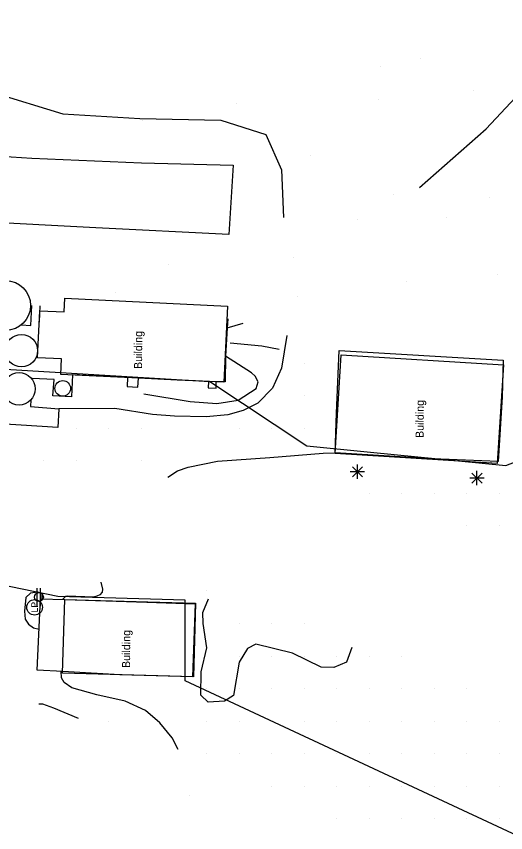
# Model space of a CAD drawing. Extents: x 19528164 to 19545171, y 7585743 to 7602745.
# Drawn here: x 19541683 to 19541984, y 7598916 to 7599418 of the extents above; entities that cross this region are included whole.
import ezdxf

# ---------------------------------------------------------------- set-up
doc = ezdxf.new("R2010")
doc.units = 0
for name, color, linetype in [('PhoAgStruc', 7, 'Continuous'), ('PhoBreakLine', 7, 'Continuous'), ('PhoBuilding', 7, 'Continuous'), ('PhoConcreteSlab', 7, 'Continuous'), ('PhoEdgeEntrancePaved', 7, 'Continuous'), ('PhoISAEPoints', 7, 'Continuous'), ('PhoNotesDesign', 7, 'Continuous'), ('PhoSurveyLimits', 7, 'Continuous'), ('PhoVegetation', 7, 'Continuous'), ('SurBreakLine', 7, 'Continuous'), ('SurEdgeEntranceUnpaved', 7, 'Continuous'), ('SurNaturalCells', 7, 'Continuous'), ('SurROWRail', 7, 'Continuous')]:
    doc.layers.add(name, color=color, linetype=linetype)

msp = doc.modelspace()

# ---------------------------------------------------------------- linework, layer by layer
at = {"layer": 'PhoAgStruc'}
for centre, radius in [((19541676.63, 7599240.45), 15.31), ((19541686.32, 7599212.7), 9.96), ((19541684.85, 7599189.24), 9.96), ((19541711.74, 7599189.49), 4.8)]:
    msp.add_circle(centre, radius, dxfattribs=at)
at = {"layer": 'PhoBreakLine'}
msp.add_line((19541751.4, 7599196.12), (19541717.68, 7599197.78), dxfattribs=at)
for points in [[(19541813.01, 7599232.3), (19541812.76, 7599226.71), (19541811.77, 7599209.21), (19541811.48, 7599193.45), (19541806.02, 7599193.45)], [(19541812.76, 7599226.71), (19541822.44, 7599229.62)], [(19541814.45, 7599217.59), (19541833.98, 7599215.72), (19541844.61, 7599213.59)], [(19541761.59, 7599186.11), (19541789.95, 7599181.37), (19541806.28, 7599180.25), (19541819.36, 7599182.32), (19541830.47, 7599189.5), (19541831.83, 7599193.45), (19541829.85, 7599197.03), (19541827.58, 7599199), (19541811.77, 7599209.21)], [(19541879.01, 7599149.94), (19541879.95, 7599174.32), (19541881.48, 7599212.82)], [(19541801.2, 7599193.69), (19541782.03, 7599194.5), (19541758.15, 7599195.79)], [(19541981.56, 7599184.36), (19541979.07, 7599144.6), (19541938.98, 7599146.13), (19541879.01, 7599149.94)], [(19541712.92, 7599059.72), (19541763.39, 7599058.11), (19541793.06, 7599057.05), (19541791.4, 7599012.18), (19541746.8, 7599013.45), (19541711.67, 7599015.6)]]:
    msp.add_lwpolyline(points, dxfattribs=at)
at = {"layer": 'PhoBuilding'}
for points in [[(19541713.02, 7599245.01), (19541812.85, 7599240.12), (19541810.56, 7599193.23), (19541710.54, 7599198.12), (19541711, 7599207.57), (19541696.21, 7599208.29), (19541697.63, 7599237.26), (19541712.61, 7599236.52)], [(19541978.6, 7599143.4), (19541878.98, 7599149.56), (19541882.73, 7599210.2), (19541982.35, 7599204.04)], [(19541712.92, 7599059.81), (19541793.27, 7599057.52), (19541791.99, 7599012.3), (19541711.64, 7599014.58)]]:
    msp.add_lwpolyline(points, close=True, dxfattribs=at)
at = {"layer": 'PhoConcreteSlab'}
for points in [[(19541751.4, 7599196.12), (19541751.22, 7599190.57), (19541757.91, 7599190.18), (19541758.15, 7599195.79)], [(19541801.2, 7599193.69), (19541800.97, 7599189.87), (19541805.92, 7599189.66), (19541806.02, 7599193.45)]]:
    msp.add_lwpolyline(points, dxfattribs=at)
at = {"layer": 'PhoEdgeEntrancePaved'}
for points in [[(19541686.25, 7599228.54), (19541692.18, 7599228.23), (19541692.82, 7599240.47)], [(19541697.61, 7599240.18), (19541697.16, 7599230.34), (19541697.29, 7599230.24)], [(19541708.71, 7599165.53), (19541673.35, 7599167.82), (19541673.13, 7599166.42), (19541666.04, 7599166.89), (19541666.9, 7599179.06), (19541672.59, 7599178.67), (19541674.19, 7599204.32), (19541652.81, 7599205.58)], [(19541717.68, 7599197.78), (19541717.16, 7599184.32), (19541705.7, 7599184.92), (19541706.39, 7599195.03), (19541692.86, 7599195.5), (19541692.85, 7599195.18)], [(19541692.18, 7599182.5), (19541691.96, 7599178.34), (19541709.25, 7599177), (19541708.71, 7599165.53)], [(19541711.67, 7599015.6), (19541695.9, 7599016.24), (19541698.04, 7599060.27), (19541712.92, 7599059.72)]]:
    msp.add_lwpolyline(points, dxfattribs=at)
at = {"layer": 'PhoISAEPoints'}
for p, q in [((19541860, 7599205), (19541860, 7599205)), ((19541860, 7599185), (19541860, 7599185)), ((19541720, 7599165), (19541720, 7599165)), ((19541740, 7599165), (19541740, 7599165)), ((19541760, 7599165), (19541760, 7599165)), ((19541820, 7599165), (19541820, 7599165)), ((19541840, 7599165), (19541840, 7599165)), ((19541860, 7599165), (19541860, 7599165)), ((19541700, 7599145), (19541700, 7599145)), ((19541720, 7599145), (19541720, 7599145)), ((19541760, 7599145), (19541760, 7599145)), ((19541900, 7599125), (19541900, 7599125)), ((19541920, 7599125), (19541920, 7599125)), ((19541940, 7599125), (19541940, 7599125)), ((19541960, 7599125), (19541960, 7599125)), ((19541980, 7599125), (19541980, 7599125)), ((19541960, 7599105), (19541960, 7599105)), ((19541980, 7599105), (19541980, 7599105)), ((19541800, 7599065), (19541800, 7599065)), ((19541820, 7599045), (19541820, 7599045)), ((19541840, 7599045), (19541840, 7599045)), ((19541860, 7599045), (19541860, 7599045)), ((19541820, 7599024.87), (19541820, 7599024.87)), ((19541840, 7599025), (19541840, 7599025)), ((19541860, 7599025), (19541860, 7599025)), ((19541880, 7599025), (19541880, 7599025)), ((19541900, 7599025), (19541900, 7599025)), ((19541920, 7599025), (19541920, 7599025)), ((19541800, 7599005), (19541800, 7599005)), ((19541820, 7599005), (19541820, 7599005)), ((19541840, 7599005), (19541840, 7599005)), ((19541860, 7599005), (19541860, 7599005)), ((19541880, 7599005), (19541880, 7599005)), ((19541900, 7599005), (19541900, 7599005)), ((19541920, 7599005), (19541920, 7599005)), ((19541940, 7599005), (19541940, 7599005)), ((19541960, 7599005), (19541960, 7599005)), ((19541740, 7598985), (19541740, 7598985)), ((19541800, 7598985), (19541800, 7598985)), ((19541820, 7598985), (19541820, 7598985)), ((19541840, 7598985), (19541840, 7598985)), ((19541860, 7598985), (19541860, 7598985)), ((19541880, 7598985), (19541880, 7598985)), ((19541900, 7598985), (19541900, 7598985)), ((19541920, 7598985), (19541920, 7598985)), ((19541940, 7598985), (19541940, 7598985)), ((19541960, 7598985), (19541960, 7598985)), ((19541980, 7598985), (19541980, 7598985)), ((19541800, 7598965), (19541800, 7598965)), ((19541820, 7598965), (19541820, 7598965)), ((19541840, 7598965), (19541840, 7598965)), ((19541860, 7598965), (19541860, 7598965)), ((19541880, 7598965), (19541880, 7598965)), ((19541900, 7598965), (19541900, 7598965)), ((19541920, 7598965), (19541920, 7598965)), ((19541940, 7598965), (19541940, 7598965)), ((19541960, 7598965), (19541960, 7598965)), ((19541980, 7598965), (19541980, 7598965)), ((19541840, 7598945), (19541840, 7598945)), ((19541860, 7598945), (19541860, 7598945)), ((19541880, 7598945), (19541880, 7598945)), ((19541900, 7598945), (19541900, 7598945)), ((19541920, 7598945), (19541920, 7598945)), ((19541940, 7598945), (19541940, 7598945)), ((19541960, 7598945), (19541960, 7598945)), ((19541980, 7598945), (19541980, 7598945)), ((19541880, 7598925), (19541880, 7598925)), ((19541900, 7598925), (19541900, 7598925)), ((19541920, 7598925), (19541920, 7598925)), ((19541940, 7598925), (19541940, 7598925)), ((19541960, 7598925), (19541960, 7598925)), ((19541980, 7598925), (19541980, 7598925))]:
    msp.add_line(p, q, dxfattribs=at)
at = {"layer": 'PhoSurveyLimits'}
msp.add_lwpolyline([(19541832.46, 7597845.39), (19542376.97, 7598092.17), (19542113.78, 7598846.31), (19542039.74, 7598891.68), (19541786.93, 7599009.68), (19541786.81, 7599059.41), (19541708.63, 7599061.66), (19541440.61, 7599116.66), (19541458.99, 7599214.49), (19541802.13, 7599193.81), (19541861.6, 7599154.2), (19541900.69, 7599150.34), (19541983.87, 7599142.12), (19543859.55, 7599862.07), (19543863.55, 7599896.16), (19543904.76, 7600247.38), (19543914.92, 7600450.3), (19543927.42, 7600632.62), (19543934.84, 7600743.15), (19543933.97, 7600882.93)], dxfattribs=at)
at = {"layer": 'PhoVegetation'}
for p, q in [((19541895.81, 7599141.37), (19541889.63, 7599135.18)), ((19541895.82, 7599135.18), (19541889.63, 7599141.36)), ((19541892.73, 7599133.9), (19541892.72, 7599142.65)), ((19541966.15, 7599130.03), (19541966.14, 7599138.78)), ((19541897.09, 7599138.28), (19541888.35, 7599138.27)), ((19541892.72, 7599138.27), (19541892.72, 7599138.27)), ((19541970.52, 7599134.41), (19541961.77, 7599134.4)), ((19541969.24, 7599131.32), (19541963.05, 7599137.49)), ((19541969.24, 7599137.5), (19541963.06, 7599131.31)), ((19541966.15, 7599134.4), (19541966.15, 7599134.4))]:
    msp.add_line(p, q, dxfattribs=at)
msp.add_lwpolyline([(19541889.31, 7599030.27), (19541885.91, 7599021.25), (19541878.21, 7599017.87), (19541870.42, 7599018.17), (19541852.86, 7599026.69), (19541830.36, 7599032.31), (19541825.2, 7599029.59), (19541820.04, 7599021.27), (19541816.52, 7599000.74), (19541811.05, 7598997.32), (19541800.94, 7598996.66), (19541796.47, 7599000.9), (19541796.77, 7599015.38), (19541800.25, 7599030.13), (19541797.96, 7599045.01), (19541797.74, 7599051.79), (19541801.27, 7599060.2)], dxfattribs=at)
at = {"layer": 'SurBreakLine'}
for points in [[(19541930.92, 7599313), (19541971.71, 7599349.07), (19541998.89, 7599377.98), (19542028.48, 7599429.47), (19542062.91, 7599497.51), (19542089.1, 7599544.66), (19542111.82, 7599579.57), (19542142.41, 7599612.54), (19542186.19, 7599651.15), (19542255.66, 7599698.78), (19542309.99, 7599746.63), (19542352.66, 7599799.39), (19542383.01, 7599842.6)], [(19541552.89, 7599257.18), (19541568.99, 7599308.86), (19541582.33, 7599341.92), (19541597.99, 7599363.5), (19541618.34, 7599376.13), (19541638.2, 7599379.64), (19541668.68, 7599371.35), (19541711.66, 7599358.25), (19541759.12, 7599355.39), (19541808.87, 7599354.27), (19541836.42, 7599345.57), (19541846.12, 7599323.84), (19541847.37, 7599294.48)], [(19541686.25, 7599228.54), (19541692.18, 7599228.23), (19541692.82, 7599240.47)], [(19541697.61, 7599240.18), (19541697.16, 7599230.34), (19541697.29, 7599230.24)], [(19541813.01, 7599232.3), (19541812.76, 7599226.71), (19541811.77, 7599209.21), (19541811.48, 7599193.45), (19541806.02, 7599193.45)], [(19541812.76, 7599226.71), (19541822.44, 7599229.62)], [(19541849.42, 7599221.94), (19541846.14, 7599201.99), (19541840.51, 7599189.56), (19541831.5, 7599180.49), (19541822.45, 7599175.97), (19541813.13, 7599173.29), (19541799.78, 7599172.1), (19541780.4, 7599172.52), (19541766.74, 7599173.42), (19541743.67, 7599177.07), (19541709.25, 7599177)], [(19541814.45, 7599217.59), (19541833.98, 7599215.72), (19541844.61, 7599213.59)], [(19541761.59, 7599186.11), (19541789.95, 7599181.37), (19541806.28, 7599180.25), (19541819.36, 7599182.32), (19541830.47, 7599189.5), (19541831.83, 7599193.45), (19541829.85, 7599197.03), (19541827.58, 7599199), (19541811.77, 7599209.21)], [(19541879.01, 7599149.94), (19541879.95, 7599174.32), (19541881.48, 7599212.82)], [(19541881.48, 7599212.82), (19541982.21, 7599206.84), (19541981.56, 7599184.36)], [(19541801.2, 7599193.69), (19541782.03, 7599194.5), (19541758.15, 7599195.79)], [(19541801.2, 7599193.69), (19541800.97, 7599189.87), (19541805.92, 7599189.66), (19541806.02, 7599193.45)], [(19541981.56, 7599184.36), (19541979.07, 7599144.6), (19541938.98, 7599146.13), (19541879.01, 7599149.94)], [(19541782.53, 7598967.59), (19541779.01, 7598974.79), (19541771.34, 7598984.02), (19541762.58, 7598991.54), (19541750.1, 7598997.3), (19541732.59, 7599001.27), (19541717.31, 7599005.54), (19541712.67, 7599008.73), (19541711.01, 7599011.66), (19541710.79, 7599015.63)]]:
    msp.add_lwpolyline(points, dxfattribs=at)
msp.add_lwpolyline([(19541813.63, 7599284.15), (19541732.13, 7599288.19), (19541658.22, 7599292.08), (19541613.98, 7599294.09), (19541616.39, 7599336.01), (19541692.81, 7599331), (19541760.01, 7599328.17), (19541816.47, 7599326.7)], close=True, dxfattribs=at)
at = {"layer": 'SurEdgeEntranceUnpaved'}
for p, q in [((19541931.17, 7599392.41), (19541931.17, 7599392.41)), ((19541906.61, 7599387.28), (19541906.61, 7599387.28)), ((19541964.22, 7599372.42), (19541964.22, 7599372.42)), ((19541818.73, 7599364.65), (19541818.73, 7599364.65)), ((19541905.35, 7599367.03), (19541905.35, 7599367.03)), ((19541760.55, 7599354.11), (19541760.55, 7599354.11)), ((19541864.06, 7599332.88), (19541864.06, 7599332.88)), ((19541914.72, 7599308.52), (19541914.72, 7599308.52)), ((19541974.09, 7599306.89), (19541974.09, 7599306.89)), ((19541947.61, 7599294.8), (19541947.61, 7599294.8)), ((19541892.56, 7599293.01), (19541892.56, 7599293.01)), ((19541853.39, 7599269.92), (19541853.39, 7599269.92)), ((19541776.71, 7599265.49), (19541776.71, 7599265.49)), ((19541978.45, 7599259.48), (19541978.45, 7599259.48)), ((19541922.85, 7599255.02), (19541922.85, 7599255.02)), ((19541744.01, 7599248.69), (19541744.01, 7599248.69)), ((19541855.93, 7599246.25), (19541855.93, 7599246.25)), ((19541860, 7599205), (19541860, 7599205)), ((19541860, 7599185), (19541860, 7599185)), ((19541860, 7599165), (19541860, 7599165)), ((19541800, 7598985), (19541800, 7598985)), ((19541820, 7598985), (19541820, 7598985)), ((19541840, 7598985), (19541840, 7598985)), ((19541800, 7598965), (19541800, 7598965)), ((19541820, 7598965), (19541820, 7598965)), ((19541840, 7598965), (19541840, 7598965)), ((19541860, 7598965), (19541860, 7598965)), ((19541880, 7598965), (19541880, 7598965)), ((19541840, 7598945), (19541840, 7598945)), ((19541860, 7598945), (19541860, 7598945)), ((19541880, 7598945), (19541880, 7598945)), ((19541900, 7598945), (19541900, 7598945)), ((19541920, 7598945), (19541920, 7598945)), ((19541789.8, 7598939.14), (19541789.8, 7598939.14)), ((19541880, 7598925), (19541880, 7598925)), ((19541900, 7598925), (19541900, 7598925)), ((19541920, 7598925), (19541920, 7598925)), ((19541940, 7598925), (19541940, 7598925)), ((19541960, 7598925), (19541960, 7598925))]:
    msp.add_line(p, q, dxfattribs=at)
at = {"layer": 'SurNaturalCells'}
for p, q in [((19541695.93, 7599055.71), (19541695.92, 7599066.7)), ((19541698.13, 7599055.71), (19541698.12, 7599066.71))]:
    msp.add_line(p, q, dxfattribs=at)
for centre, radius in [((19541697.03, 7599061.21), 2.76), ((19541694.41, 7599054.95), 4.8)]:
    msp.add_circle(centre, radius, dxfattribs=at)
at = {"layer": 'SurROWRail'}
for points in [[(19541849.42, 7599221.94), (19541846.14, 7599201.99), (19541840.51, 7599189.56), (19541831.5, 7599180.49), (19541822.45, 7599175.97), (19541813.13, 7599173.29), (19541799.78, 7599172.1), (19541780.4, 7599172.52), (19541766.74, 7599173.42), (19541743.67, 7599177.07), (19541709.25, 7599177)], [(19541776.32, 7599135.01), (19541782.18, 7599138.78), (19541788.79, 7599141.1), (19541806.86, 7599144.88), (19541838.93, 7599147.02), (19541871.67, 7599149.72), (19541879.01, 7599149.94)], [(19541735.14, 7599070.39), (19541736.19, 7599066.15), (19541735.89, 7599064.22), (19541734.54, 7599062.73), (19541732.74, 7599061.81), (19541730.51, 7599061.15), (19541714.49, 7599061.88), (19541713.31, 7599061.53), (19541711.55, 7599059.77)], [(19541699.15, 7599060.23), (19541699.06, 7599063.25), (19541696.48, 7599064.21), (19541691.97, 7599063.64), (19541689.13, 7599060.97), (19541688.18, 7599052.69), (19541688.62, 7599047.75), (19541690.59, 7599044.51), (19541693.83, 7599042.37), (19541697.13, 7599041.6)], [(19541782.53, 7598967.59), (19541779.01, 7598974.79), (19541771.34, 7598984.02), (19541762.58, 7598991.54), (19541750.1, 7598997.3), (19541732.59, 7599001.27), (19541717.31, 7599005.54), (19541712.67, 7599008.73), (19541711.01, 7599011.66), (19541710.79, 7599015.63)], [(19541697.06, 7598995.58), (19541699.34, 7598995.55), (19541705.95, 7598993.19), (19541721.27, 7598986.73)]]:
    msp.add_lwpolyline(points, dxfattribs=at)

# ---------------------------------------------------------------- texts
at = {"layer": 'PhoNotesDesign'}
for p in [(19541760.4, 7599201.41), (19541933.36, 7599159.01), (19541753.04, 7599017.64)]:
    msp.add_text('Building', height=4.92, rotation=89.5617, dxfattribs=at).set_placement(p)
at = {"layer": 'SurNaturalCells'}
msp.add_text('LP', height=3.999, rotation=90.0576, dxfattribs=at).set_placement((19541696.41, 7599051.77))

doc.saveas('drawing.dxf')
